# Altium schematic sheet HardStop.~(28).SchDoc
size A
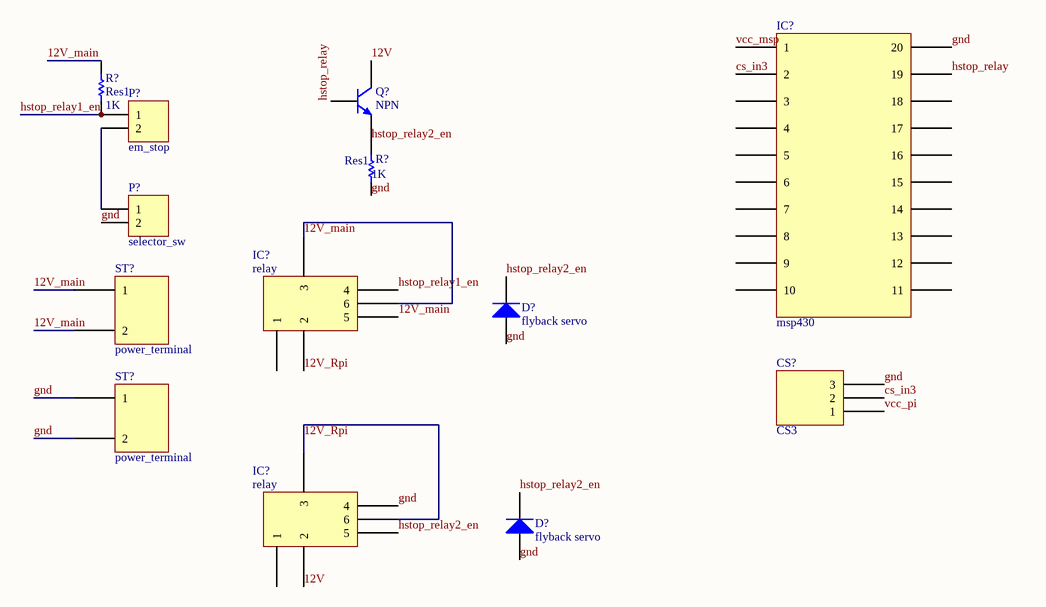
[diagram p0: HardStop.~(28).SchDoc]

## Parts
(Parts that share a designator on the sheet are numbered #1, #2 ... from top to bottom, then left to right.)
CS?  CS3  [ACS712]
D?#1  flyback servo  [DO-41]
D?#2  flyback servo  [DO-41]
IC?#1  msp430  [msp430]
IC?#2  relay  [relay JQX 15F]
IC?#3  relay  [relay JQX 15F]
P?#1  em_stop  [HDR1X2H]
P?#2  selector_sw  [HDR1X2H]
Q?  NPN  [TO-226-AA]
R?#1  Res1  value 1K  [AXIAL-0.3]
R?#2  Res1  value 1K  [AXIAL-0.3]
ST?#1  power_terminal  [screw_terminal_5]
ST?#2  power_terminal  [screw_terminal_5]

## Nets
12V: IC?#3.2 Q?.1(C)
12V_main: IC?#2.3 IC?#2.5 IC?#2.6 R?#1.2 ST?#1.1 ST?#1.2
12V_Rpi: IC?#2.2 IC?#3.3 IC?#3.6
cs_in3: CS?.2 IC?#1.2
gnd: CS?.3 D?#1.1(A) D?#2.1(A) IC?#1.20 IC?#3.4 P?#2.2 R?#2.1 ST?#2.1 ST?#2.2
hstop_relay: IC?#1.19 Q?.2(B)
hstop_relay1_en: IC?#2.4 P?#1.1 R?#1.1
hstop_relay2_en: D?#1.2(K) D?#2.2(K) IC?#3.5 Q?.3(E) R?#2.2
vcc_msp: IC?#1.1
vcc_pi: CS?.1
NetP?#1_2: P?#1.2 P?#2.1

Not connected (* = marked no-connect by the designer): IC?#1 3 4 5 6 7 8 9 10 11 12 13 14 15 16 17 18; IC?#2 1; IC?#3 1

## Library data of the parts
CS? = ACS712
D?#1 D?#2 = Diode 1N4001: 1 Amp General Purpose Rectifier
IC?#2 IC?#3 = relay JQX-15F
P?#1 P?#2 = Header 2H: Header, 2-Pin, Right Angle
Q? = NPN: NPN Bipolar Transistor
R?#1 R?#2 = Res1: Resistor
ST?#1 ST?#2 = screw_terminal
